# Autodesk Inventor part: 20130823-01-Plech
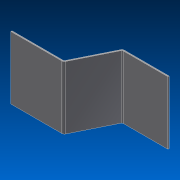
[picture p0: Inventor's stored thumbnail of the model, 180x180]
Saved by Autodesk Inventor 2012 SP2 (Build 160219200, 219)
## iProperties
Created: 2013-08
Part Number: 20130823-01-Plech
Material: Default
Document SubType Name: Plech
Designer: navara
Mass: 0.705088 g
Surface Area: 29.0176 cm^2
Volume: 0.705088 cm^3
Density: 1 g/cm^3
Sheet Metal Rule: Výchozí_mm
LastSaveDate: 12.04.2011
SM_Extents: 0x0
SM_Thickness: 0,5
SM_Length: 0
SM_Width: 0
SM_Style: Default_mm
VAHA: 0 kg
ROZMER_4: 0x0
Author: navara
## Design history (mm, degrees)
node "Profilový ohyb1"
  sketch "Náčrt1"
    geometry: L1 (0, 0)-(20.651, 0); L2 (20.651, 0)-(28.411, 15.676); L3 (28.411, 15.676)-(46.871, 15.676); 1 further point
    constraints: 6 end point, 1 horizontal, 1 parallel
node "Těleso1"
feature "Deska1" dims "d0" = 0.5 (= ŠířkaVýštipu), "d1" = 0.25 (= HloubkaVýštipu), "d2" = 1 (= MinimálníZbytek), "d3" = 0.5 (= PoloměrOhybu), "d4" = 25, "d5" = 0.5 (= PoloměrOhybu), "d6" = 0.5, "d7" = 2 (= VelikostRohovéhoVýštipu), "d8" = 0.5 (= VelikostMezery), "d9" = 0.5 (= VelikostJacobihoPoloměru), "Tloušťka" = 0.5 (derived), "MezeraVystřižení" = 0.01
feature "Ohyb1" dims "d0" = 0.5 (= ŠířkaVýštipu), "d1" = 0.25 (= HloubkaVýštipu), "d2" = 1 (= MinimálníZbytek), "d3" = 0.5 (= PoloměrOhybu), "d5" = 0.5 (= PoloměrOhybu), "d6" = 0.5, "Tloušťka" = 0.5 (derived), "MezeraVystřižení" = 0.01
feature "Roh1" dims "d6" = 0.5, "d7" = 2 (= VelikostRohovéhoVýštipu), "d8" = 0.5 (= VelikostMezery), "d9" = 0.5 (= VelikostJacobihoPoloměru)
other parameters: "KSoučinitel" = 4.4, "PoloměrOhybu" = 0.5 (= Tloušťka), "ŠířkaVýštipu" = 0.5 (= Tloušťka), "HloubkaVýštipu" = 0.25 (= 0.5 x Tloušťka), "VelikostRohovéhoVýštipu" = 2 (= 4 x Tloušťka), "MinimálníZbytek" = 1 (= 2 x Tloušťka), "PřechodovýPoloměr" = 0.5 (= PoloměrOhybu), "VelikostJacobihoPoloměru" = 0.5 (= PoloměrOhybu), "VelikostMezery" = 0.5 (= Tloušťka)
